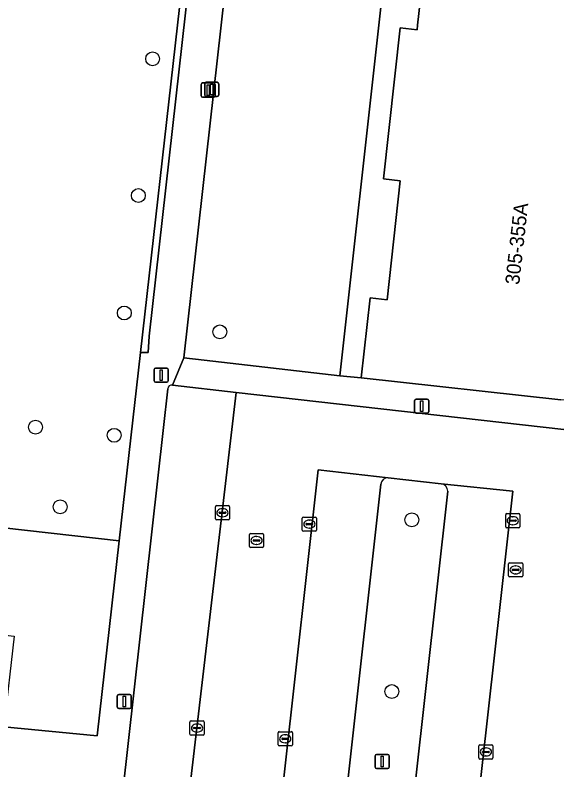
# Model space of a CAD drawing. Extents: x 161928 to 163071, y 386474 to 387428.
# Drawn here: x 162020.1 to 162058.3, y 386697.5 to 386750.7 of the extents above; entities that cross this region are included whole.
import ezdxf

# ---------------------------------------------------------------- set-up
doc = ezdxf.new("R2010")
doc.units = 0
for name, color, linetype in [('IMGEO_Boom', 7, 'Continuous'), ('IMGEO_Erf', 7, 'Continuous'), ('IMGEO_Groenvoorziening', 7, 'Continuous'), ('IMGEO_Kolk', 7, 'Continuous'), ('IMGEO_Lichtmast', 7, 'Continuous'), ('IMGEO_Pand', 7, 'Continuous'), ('IMGEO_Pand_nummerreeks', 7, 'Continuous'), ('IMGEO_Parkeervlak_open', 7, 'Continuous'), ('IMGEO_Rijbaan_lokaal_open', 7, 'Continuous'), ('IMGEO_Rioolput', 7, 'Continuous'), ('IMGEO_Voetpad_open', 7, 'Continuous')]:
    doc.layers.add(name, color=color, linetype=linetype)

msp = doc.modelspace()

# ---------------------------------------------------------------- linework, layer by layer
at = {"layer": 'IMGEO_Boom'}
for centre in [(162029.798, 386747.617), (162028.793, 386737.977), (162027.801, 386729.696), (162034.543, 386728.362), (162021.54, 386721.644), (162027.088, 386721.072), (162023.278, 386716.03), (162048.08, 386715.113), (162046.668, 386702.996)]:
    msp.add_circle(centre, 0.489, dxfattribs=at)
at = {"layer": 'IMGEO_Erf'}
msp.add_lwpolyline([(162044.512, 386725.13), (162045.14, 386730.766), (162046.333, 386730.634), (162047.268, 386739.022), (162046.075, 386739.154), (162047.261, 386749.807), (162048.454, 386749.675), (162048.49, 386750), (162049.389, 386758.073), (162048.195, 386758.205), (162048.824, 386763.85), (162047.299, 386764.081), (162045.743, 386750), (162043.01, 386725.268)], close=True, dxfattribs=at)
at = {"layer": 'IMGEO_Groenvoorziening'}
for points in [[(162031.554, 386750), (162033.319, 386765.609), (162026.736, 386766.372), (162021.82, 386766.942), (162021.773, 386766.325), (162007.448, 386767.992), (162006.241, 386755.742), (162005.304, 386755.813), (162005.214, 386755.021), (162004.653, 386750), (162000.921, 386716.619), (162027.442, 386713.619), (162028.943, 386726.903)], [(162045.743, 386750), (162047.299, 386764.081), (162036.361, 386765.29), (162034.645, 386750), (162032.012, 386726.545), (162033.433, 386726.38), (162043.01, 386725.268)], [(162027.442, 386713.619), (162000.921, 386716.619), (162000.892, 386716.355), (162002.809, 386716.141), (162002.552, 386713.863), (162018.281, 386712.103), (162017.75, 386707.17), (162020.04, 386706.893), (162019.314, 386700.509), (162025.888, 386699.876)]]:
    msp.add_lwpolyline(points, close=True, dxfattribs=at)
for points in [[(162050.156, 386717.652), (162046.414, 386718.074)], [(162045.889, 386717.614), (162041.265, 386675.985)], [(162045.986, 386675.583), (162050.625, 386717.141)]]:
    msp.add_lwpolyline(points, dxfattribs=at)
for centre, radius, start, end in [((162046.415, 386717.544), 0.53, 90.0572, 172.3919), ((162050.075, 386717.107), 0.551, 3.5466, 81.5454)]:
    msp.add_arc(centre, radius, start, end, dxfattribs=at)
at = {"layer": 'IMGEO_Kolk'}
for p, q in [((162034.223, 386715.183), (162034.223, 386716.035)), ((162034.298, 386716.109), (162035.15, 386716.109)), ((162034.711, 386715.889), (162034.736, 386715.889)), ((162035.224, 386716.035), (162035.224, 386715.183)), ((162034.482, 386715.603), (162034.482, 386715.615)), ((162034.92, 386715.566), (162034.522, 386715.566)), ((162034.525, 386715.652), (162034.923, 386715.652)), ((162034.734, 386715.329), (162034.709, 386715.329)), ((162034.966, 386715.615), (162034.966, 386715.603)), ((162040.355, 386714.38), (162040.355, 386715.232)), ((162040.43, 386715.306), (162041.282, 386715.306)), ((162041.356, 386715.232), (162041.356, 386714.38)), ((162054.697, 386714.621), (162054.697, 386715.473)), ((162054.772, 386715.547), (162055.624, 386715.547)), ((162055.185, 386715.327), (162055.21, 386715.327)), ((162055.698, 386715.473), (162055.698, 386714.621)), ((162035.15, 386715.109), (162034.298, 386715.109)), ((162040.614, 386714.8), (162040.614, 386714.812)), ((162041.052, 386714.763), (162040.654, 386714.763)), ((162040.657, 386714.849), (162041.055, 386714.849)), ((162040.843, 386715.086), (162040.868, 386715.086)), ((162041.098, 386714.812), (162041.098, 386714.8)), ((162054.956, 386715.041), (162054.956, 386715.053)), ((162055.394, 386715.004), (162054.996, 386715.004)), ((162054.999, 386715.09), (162055.397, 386715.09)), ((162055.208, 386714.767), (162055.183, 386714.767)), ((162055.44, 386715.053), (162055.44, 386715.041)), ((162041.282, 386714.306), (162040.43, 386714.306)), ((162040.866, 386714.526), (162040.841, 386714.526)), ((162055.624, 386714.547), (162054.772, 386714.547)), ((162032.433, 386699.998), (162032.433, 386700.85)), ((162032.508, 386700.924), (162033.36, 386700.924)), ((162033.434, 386700.85), (162033.434, 386699.998)), ((162032.692, 386700.418), (162032.692, 386700.43)), ((162033.13, 386700.381), (162032.732, 386700.381)), ((162032.735, 386700.467), (162033.133, 386700.467)), ((162032.921, 386700.704), (162032.946, 386700.704)), ((162033.176, 386700.43), (162033.176, 386700.418)), ((162033.36, 386699.924), (162032.508, 386699.924)), ((162032.944, 386700.144), (162032.919, 386700.144)), ((162038.654, 386699.243), (162038.654, 386700.095)), ((162038.729, 386700.169), (162039.581, 386700.169)), ((162039.142, 386699.949), (162039.167, 386699.949)), ((162039.655, 386700.095), (162039.655, 386699.243)), ((162038.913, 386699.663), (162038.913, 386699.675)), ((162039.351, 386699.626), (162038.953, 386699.626)), ((162038.956, 386699.712), (162039.354, 386699.712)), ((162039.165, 386699.389), (162039.14, 386699.389)), ((162039.397, 386699.675), (162039.397, 386699.663)), ((162052.873, 386699.239), (162053.725, 386699.239)), ((162039.581, 386699.169), (162038.729, 386699.169)), ((162052.798, 386698.313), (162052.798, 386699.165)), ((162053.057, 386698.733), (162053.057, 386698.745)), ((162053.495, 386698.696), (162053.097, 386698.696)), ((162053.1, 386698.782), (162053.498, 386698.782)), ((162053.286, 386699.019), (162053.311, 386699.019)), ((162053.541, 386698.745), (162053.541, 386698.733)), ((162053.799, 386699.165), (162053.799, 386698.313)), ((162053.725, 386698.239), (162052.873, 386698.239)), ((162053.309, 386698.459), (162053.284, 386698.459))]:
    msp.add_line(p, q, dxfattribs=at)
for points in [[(162034.223, 386715.183), (162034.223, 386716.035)], [(162034.298, 386716.109), (162035.15, 386716.109)], [(162035.224, 386716.035), (162035.224, 386715.183)], [(162040.355, 386714.38), (162040.355, 386715.232)], [(162040.43, 386715.306), (162041.282, 386715.306)], [(162041.356, 386715.232), (162041.356, 386714.38)], [(162054.697, 386714.621), (162054.697, 386715.473)], [(162054.772, 386715.547), (162055.624, 386715.547)], [(162055.698, 386715.473), (162055.698, 386714.621)], [(162035.15, 386715.109), (162034.298, 386715.109)], [(162041.282, 386714.306), (162040.43, 386714.306)], [(162055.624, 386714.547), (162054.772, 386714.547)], [(162032.433, 386699.998), (162032.433, 386700.85)], [(162032.508, 386700.924), (162033.36, 386700.924)], [(162033.434, 386700.85), (162033.434, 386699.998)], [(162033.36, 386699.924), (162032.508, 386699.924)], [(162038.654, 386699.243), (162038.654, 386700.095)], [(162038.729, 386700.169), (162039.581, 386700.169)], [(162039.655, 386700.095), (162039.655, 386699.243)], [(162052.873, 386699.239), (162053.725, 386699.239)], [(162039.581, 386699.169), (162038.729, 386699.169)], [(162052.798, 386698.313), (162052.798, 386699.165)], [(162053.799, 386699.165), (162053.799, 386698.313)], [(162053.725, 386698.239), (162052.873, 386698.239)]]:
    msp.add_lwpolyline(points, dxfattribs=at)
for centre, radius, start, end in [((162034.3, 386716.033), 0.0765, 91.552, 178.448), ((162034.3, 386716.033), 0.0765, 91.552, 178.448), ((162035.148, 386716.033), 0.0765, 1.552, 88.448), ((162035.148, 386716.033), 0.0765, 1.552, 88.448), ((162034.3, 386715.185), 0.0765, 181.552, 268.448), ((162034.3, 386715.185), 0.0765, 181.552, 268.448), ((162034.522, 386715.612), 0.0403, 85.8775, 175.7526), ((162034.519, 386715.602), 0.0366, 178.938, 274.7102), ((162034.923, 386715.609), 0.043, 264.8664, 352.4533), ((162034.927, 386715.614), 0.0386, 1.7309, 96.639), ((162035.148, 386715.185), 0.0765, 271.552, 358.448), ((162035.148, 386715.185), 0.0765, 271.552, 358.448), ((162040.432, 386715.23), 0.0765, 91.552, 178.448), ((162040.432, 386715.23), 0.0765, 91.552, 178.448), ((162041.28, 386715.23), 0.0765, 1.552, 88.448), ((162041.28, 386715.23), 0.0765, 1.552, 88.448), ((162054.774, 386715.471), 0.0765, 91.552, 178.448), ((162054.774, 386715.471), 0.0765, 91.552, 178.448), ((162055.622, 386715.471), 0.0765, 1.552, 88.448), ((162055.622, 386715.471), 0.0765, 1.552, 88.448), ((162040.654, 386714.809), 0.0403, 85.8775, 175.7526), ((162040.651, 386714.799), 0.0366, 178.938, 274.7102), ((162041.055, 386714.806), 0.043, 264.8664, 352.4533), ((162041.059, 386714.811), 0.0386, 1.7309, 96.639), ((162054.996, 386715.05), 0.0403, 85.8775, 175.7526), ((162054.993, 386715.04), 0.0366, 178.938, 274.7102), ((162055.397, 386715.047), 0.043, 264.8664, 352.4533), ((162055.401, 386715.052), 0.0386, 1.7309, 96.639), ((162040.432, 386714.382), 0.0765, 181.552, 268.448), ((162040.432, 386714.382), 0.0765, 181.552, 268.448), ((162041.28, 386714.382), 0.0765, 271.552, 358.448), ((162041.28, 386714.382), 0.0765, 271.552, 358.448), ((162054.774, 386714.623), 0.0765, 181.552, 268.448), ((162054.774, 386714.623), 0.0765, 181.552, 268.448), ((162055.622, 386714.623), 0.0765, 271.552, 358.448), ((162055.622, 386714.623), 0.0765, 271.552, 358.448), ((162032.51, 386700.848), 0.0765, 91.552, 178.448), ((162032.51, 386700.848), 0.0765, 91.552, 178.448), ((162033.358, 386700.848), 0.0765, 1.552, 88.448), ((162033.358, 386700.848), 0.0765, 1.552, 88.448), ((162032.732, 386700.427), 0.0403, 85.8775, 175.7526), ((162032.729, 386700.417), 0.0366, 178.938, 274.7102), ((162033.133, 386700.424), 0.043, 264.8664, 352.4533), ((162033.137, 386700.429), 0.0386, 1.7309, 96.639), ((162032.51, 386700), 0.0765, 181.552, 268.448), ((162032.51, 386700), 0.0765, 181.552, 268.448), ((162033.358, 386700), 0.0765, 271.552, 358.448), ((162033.358, 386700), 0.0765, 271.552, 358.448), ((162038.731, 386700.093), 0.0765, 91.552, 178.448), ((162038.731, 386700.093), 0.0765, 91.552, 178.448), ((162039.579, 386700.093), 0.0765, 1.552, 88.448), ((162039.579, 386700.093), 0.0765, 1.552, 88.448), ((162038.731, 386699.245), 0.0765, 181.552, 268.448), ((162038.731, 386699.245), 0.0765, 181.552, 268.448), ((162038.953, 386699.672), 0.0403, 85.8775, 175.7526), ((162038.95, 386699.662), 0.0366, 178.938, 274.7102), ((162039.354, 386699.669), 0.043, 264.8664, 352.4533), ((162039.358, 386699.674), 0.0386, 1.7309, 96.639), ((162039.579, 386699.245), 0.0765, 271.552, 358.448), ((162039.579, 386699.245), 0.0765, 271.552, 358.448), ((162052.875, 386699.163), 0.0765, 91.552, 178.448), ((162052.875, 386699.163), 0.0765, 91.552, 178.448), ((162053.723, 386699.163), 0.0765, 1.552, 88.448), ((162053.723, 386699.163), 0.0765, 1.552, 88.448), ((162053.097, 386698.742), 0.0403, 85.8775, 175.7526), ((162053.094, 386698.732), 0.0366, 178.938, 274.7102), ((162053.498, 386698.739), 0.043, 264.8664, 352.4533), ((162053.502, 386698.744), 0.0386, 1.7309, 96.639), ((162052.875, 386698.315), 0.0765, 181.552, 268.448), ((162052.875, 386698.315), 0.0765, 181.552, 268.448), ((162053.723, 386698.315), 0.0765, 271.552, 358.448), ((162053.723, 386698.315), 0.0765, 271.552, 358.448)]:
    msp.add_arc(centre, radius, start, end, dxfattribs=at)
for centre, major_axis, ratio, start_param, end_param in [((162034.71, 386715.609), (-0.387, 0.002), 0.722429, 4.712389, 7.853982), ((162034.735, 386715.609), (-0.39, 0.002), 0.717154, 1.570796, 4.712389), ((162055.184, 386715.047), (-0.387, 0.002), 0.722429, 4.712389, 7.853982), ((162055.209, 386715.047), (-0.39, 0.002), 0.717154, 1.570796, 4.712389), ((162040.842, 386714.806), (-0.387, 0.002), 0.722429, 4.712389, 7.853982), ((162040.867, 386714.806), (-0.39, 0.002), 0.717154, 1.570796, 4.712389), ((162032.92, 386700.424), (-0.387, 0.002), 0.722429, 4.712389, 7.853982), ((162032.945, 386700.424), (-0.39, 0.002), 0.717154, 1.570796, 4.712389), ((162039.141, 386699.669), (-0.387, 0.002), 0.722429, 4.712389, 7.853982), ((162039.166, 386699.669), (-0.39, 0.002), 0.717154, 1.570796, 4.712389), ((162053.285, 386698.739), (-0.387, 0.002), 0.722429, 4.712389, 7.853982), ((162053.31, 386698.739), (-0.39, 0.002), 0.717154, 1.570796, 4.712389)]:
    msp.add_ellipse(centre, major_axis=major_axis, ratio=ratio, start_param=start_param, end_param=end_param, dxfattribs=at)
at = {"layer": 'IMGEO_Lichtmast'}
for p, q in [((162033.228, 386745.019), (162033.228, 386745.819)), ((162033.228, 386745.819), (162033.228, 386745.019)), ((162033.328, 386745.919), (162034.118, 386745.919)), ((162034.118, 386745.919), (162033.328, 386745.919)), ((162033.47, 386745.068), (162033.47, 386745.868)), ((162033.47, 386745.868), (162033.47, 386745.068)), ((162033.57, 386745.968), (162034.36, 386745.968)), ((162034.36, 386745.968), (162033.57, 386745.968)), ((162034.218, 386745.819), (162034.218, 386745.019)), ((162034.218, 386745.019), (162034.218, 386745.819)), ((162034.46, 386745.868), (162034.46, 386745.068)), ((162034.46, 386745.068), (162034.46, 386745.868)), ((162034.118, 386744.919), (162033.328, 386744.919)), ((162033.328, 386744.919), (162034.118, 386744.919)), ((162034.36, 386744.968), (162033.57, 386744.968)), ((162033.57, 386744.968), (162034.36, 386744.968)), ((162029.908, 386724.916), (162029.908, 386725.716)), ((162029.908, 386725.716), (162029.908, 386724.916)), ((162030.008, 386725.816), (162030.798, 386725.816)), ((162030.798, 386725.816), (162030.008, 386725.816)), ((162030.898, 386725.716), (162030.898, 386724.916)), ((162030.898, 386724.916), (162030.898, 386725.716)), ((162030.798, 386724.816), (162030.008, 386724.816)), ((162030.008, 386724.816), (162030.798, 386724.816)), ((162048.279, 386722.73), (162048.279, 386723.53)), ((162048.279, 386723.53), (162048.279, 386722.73)), ((162048.379, 386723.63), (162049.169, 386723.63)), ((162049.169, 386723.63), (162048.379, 386723.63)), ((162049.269, 386723.53), (162049.269, 386722.73)), ((162049.269, 386722.73), (162049.269, 386723.53)), ((162049.169, 386722.63), (162048.379, 386722.63)), ((162048.379, 386722.63), (162049.169, 386722.63)), ((162027.308, 386701.9), (162027.308, 386702.7)), ((162027.308, 386702.7), (162027.308, 386701.9)), ((162027.408, 386702.8), (162028.198, 386702.8)), ((162028.198, 386702.8), (162027.408, 386702.8)), ((162028.298, 386702.7), (162028.298, 386701.9)), ((162028.298, 386701.9), (162028.298, 386702.7)), ((162028.198, 386701.8), (162027.408, 386701.8)), ((162027.408, 386701.8), (162028.198, 386701.8)), ((162045.489, 386697.665), (162045.489, 386698.465)), ((162045.489, 386698.465), (162045.489, 386697.665)), ((162045.589, 386698.565), (162046.379, 386698.565)), ((162046.379, 386698.565), (162045.589, 386698.565)), ((162046.479, 386698.465), (162046.479, 386697.665)), ((162046.479, 386697.665), (162046.479, 386698.465)), ((162046.379, 386697.565), (162045.589, 386697.565)), ((162045.589, 386697.565), (162046.379, 386697.565))]:
    msp.add_line(p, q, dxfattribs=at)
for points in [[(162033.648, 386745.794), (162033.798, 386745.794), (162033.798, 386745.044), (162033.648, 386745.044), (162033.648, 386745.794)], [(162033.89, 386745.843), (162034.04, 386745.843), (162034.04, 386745.093), (162033.89, 386745.093), (162033.89, 386745.843)], [(162030.328, 386725.691), (162030.478, 386725.691), (162030.478, 386724.941), (162030.328, 386724.941), (162030.328, 386725.691)], [(162048.699, 386723.505), (162048.849, 386723.505), (162048.849, 386722.755), (162048.699, 386722.755), (162048.699, 386723.505)], [(162027.728, 386702.675), (162027.878, 386702.675), (162027.878, 386701.925), (162027.728, 386701.925), (162027.728, 386702.675)], [(162045.909, 386698.44), (162046.059, 386698.44), (162046.059, 386697.69), (162045.909, 386697.69), (162045.909, 386698.44)]]:
    msp.add_lwpolyline(points, dxfattribs=at)
for centre, start, end in [((162033.328, 386745.819), 90, 180), ((162033.328, 386745.819), 90, 180), ((162033.57, 386745.868), 90, 180), ((162033.57, 386745.868), 90, 180), ((162034.118, 386745.819), 0, 90), ((162034.118, 386745.819), 360, 90), ((162034.36, 386745.868), 0, 90), ((162034.36, 386745.868), 360, 90), ((162033.328, 386745.019), 180, 270), ((162033.328, 386745.019), 180, 270), ((162033.57, 386745.068), 180, 270), ((162033.57, 386745.068), 180, 270), ((162034.118, 386745.019), 270, 0), ((162034.118, 386745.019), 270, 0), ((162034.36, 386745.068), 270, 0), ((162034.36, 386745.068), 270, 0), ((162030.008, 386725.716), 90, 180), ((162030.008, 386725.716), 90, 180), ((162030.798, 386725.716), 0, 90), ((162030.798, 386725.716), 360, 90), ((162030.008, 386724.916), 180, 270), ((162030.008, 386724.916), 180, 270), ((162030.798, 386724.916), 270, 0), ((162030.798, 386724.916), 270, 0), ((162048.379, 386723.53), 90, 180), ((162048.379, 386723.53), 90, 180), ((162049.169, 386723.53), 0, 90), ((162049.169, 386723.53), 360, 90), ((162048.379, 386722.73), 180, 270), ((162048.379, 386722.73), 180, 270), ((162049.169, 386722.73), 270, 0), ((162049.169, 386722.73), 270, 0), ((162027.408, 386702.7), 90, 180), ((162027.408, 386702.7), 90, 180), ((162028.198, 386702.7), 0, 90), ((162028.198, 386702.7), 360, 90), ((162027.408, 386701.9), 180, 270), ((162027.408, 386701.9), 180, 270), ((162028.198, 386701.9), 270, 0), ((162028.198, 386701.9), 270, 0), ((162045.589, 386698.465), 90, 180), ((162045.589, 386698.465), 90, 180), ((162046.379, 386698.465), 0, 90), ((162046.379, 386698.465), 360, 90), ((162045.589, 386697.665), 180, 270), ((162045.589, 386697.665), 180, 270), ((162046.379, 386697.665), 270, 0), ((162046.379, 386697.665), 270, 0)]:
    msp.add_arc(centre, 0.1, start, end, dxfattribs=at)
at = {"layer": 'IMGEO_Pand'}
msp.add_lwpolyline([(162062.945, 386762.278), (162048.824, 386763.85), (162048.195, 386758.205), (162049.389, 386758.073), (162048.49, 386750), (162048.454, 386749.675), (162047.261, 386749.807), (162046.075, 386739.154), (162047.268, 386739.022), (162046.333, 386730.634), (162045.14, 386730.766), (162044.512, 386725.13), (162058.594, 386723.562)], dxfattribs=at)
at = {"layer": 'IMGEO_Parkeervlak_open'}
for points in [[(162030.861, 386724.346), (162030.559, 386721.622), (162025.596, 386677.256), (162029.178, 386676.854), (162030.14, 386676.772), (162035.688, 386724.098)], [(162035.688, 386724.098), (162031.198, 386724.615)], [(162046.414, 386718.074), (162041.463, 386718.633), (162036.718, 386676.03), (162041.695, 386675.5)], [(162041.265, 386675.985), (162045.889, 386717.614)], [(162055.206, 386717.137), (162050.156, 386717.652)], [(162045.448, 386675.119), (162050.462, 386674.649), (162055.206, 386717.137)], [(162050.625, 386717.141), (162045.986, 386675.583)]]:
    msp.add_lwpolyline(points, dxfattribs=at)
for centre, radius, start, end in [((162031.164, 386724.312), 0.305, 83.6127, 173.5824), ((162046.415, 386717.544), 0.53, 90.0572, 172.3919), ((162050.075, 386717.107), 0.551, 3.5466, 81.5454)]:
    msp.add_arc(centre, radius, start, end, dxfattribs=at)
at = {"layer": 'IMGEO_Rijbaan_lokaal_open'}
msp.add_lwpolyline([(162061.719, 386721.152), (162035.688, 386724.098), (162030.14, 386676.772), (162029.178, 386676.854), (162025.596, 386677.256), (162021.441, 386677.722), (162020.162, 386677.862)], dxfattribs=at)
msp.add_lwpolyline([(162046.414, 386718.074), (162050.156, 386717.652), (162055.206, 386717.137), (162050.462, 386674.649), (162045.448, 386675.119), (162041.695, 386675.5), (162036.718, 386676.03), (162041.463, 386718.633)], close=True, dxfattribs=at)
at = {"layer": 'IMGEO_Rioolput'}
for p, q in [((162036.701, 386714.152), (162037.553, 386714.152)), ((162036.626, 386713.226), (162036.626, 386714.078)), ((162036.885, 386713.646), (162036.885, 386713.658)), ((162037.323, 386713.609), (162036.925, 386713.609)), ((162036.928, 386713.695), (162037.326, 386713.695)), ((162037.114, 386713.932), (162037.139, 386713.932)), ((162037.369, 386713.658), (162037.369, 386713.646)), ((162037.627, 386714.078), (162037.627, 386713.226)), ((162037.553, 386713.152), (162036.701, 386713.152)), ((162037.137, 386713.372), (162037.112, 386713.372)), ((162054.9, 386711.154), (162054.9, 386712.006)), ((162054.975, 386712.08), (162055.827, 386712.08)), ((162055.901, 386712.006), (162055.901, 386711.154)), ((162055.159, 386711.574), (162055.159, 386711.586)), ((162055.597, 386711.537), (162055.199, 386711.537)), ((162055.202, 386711.623), (162055.6, 386711.623)), ((162055.388, 386711.86), (162055.413, 386711.86)), ((162055.643, 386711.586), (162055.643, 386711.574)), ((162055.827, 386711.08), (162054.975, 386711.08)), ((162055.411, 386711.3), (162055.386, 386711.3))]:
    msp.add_line(p, q, dxfattribs=at)
for points in [[(162036.701, 386714.152), (162037.553, 386714.152)], [(162036.626, 386713.226), (162036.626, 386714.078)], [(162037.627, 386714.078), (162037.627, 386713.226)], [(162037.553, 386713.152), (162036.701, 386713.152)], [(162054.9, 386711.154), (162054.9, 386712.006)], [(162054.975, 386712.08), (162055.827, 386712.08)], [(162055.901, 386712.006), (162055.901, 386711.154)], [(162055.827, 386711.08), (162054.975, 386711.08)]]:
    msp.add_lwpolyline(points, dxfattribs=at)
for centre, radius, start, end in [((162036.703, 386714.076), 0.0765, 91.552, 178.448), ((162036.703, 386714.076), 0.0765, 91.552, 178.448), ((162037.551, 386714.076), 0.0765, 1.552, 88.448), ((162037.551, 386714.076), 0.0765, 1.552, 88.448), ((162036.925, 386713.655), 0.0403, 85.8775, 175.7526), ((162036.922, 386713.645), 0.0366, 178.938, 274.7102), ((162037.326, 386713.652), 0.043, 264.8664, 352.4533), ((162037.33, 386713.657), 0.0386, 1.7309, 96.639), ((162036.703, 386713.228), 0.0765, 181.552, 268.448), ((162036.703, 386713.228), 0.0765, 181.552, 268.448), ((162037.551, 386713.228), 0.0765, 271.552, 358.448), ((162037.551, 386713.228), 0.0765, 271.552, 358.448), ((162054.977, 386712.004), 0.0765, 91.552, 178.448), ((162054.977, 386712.004), 0.0765, 91.552, 178.448), ((162055.825, 386712.004), 0.0765, 1.552, 88.448), ((162055.825, 386712.004), 0.0765, 1.552, 88.448), ((162055.199, 386711.583), 0.0403, 85.8775, 175.7526), ((162055.196, 386711.573), 0.0366, 178.938, 274.7102), ((162055.6, 386711.58), 0.043, 264.8664, 352.4533), ((162055.604, 386711.585), 0.0386, 1.7309, 96.639), ((162054.977, 386711.156), 0.0765, 181.552, 268.448), ((162054.977, 386711.156), 0.0765, 181.552, 268.448), ((162055.825, 386711.156), 0.0765, 271.552, 358.448), ((162055.825, 386711.156), 0.0765, 271.552, 358.448)]:
    msp.add_arc(centre, radius, start, end, dxfattribs=at)
for centre, major_axis, ratio, start_param, end_param in [((162037.113, 386713.652), (-0.387, 0.002), 0.722429, 4.712389, 7.853982), ((162037.138, 386713.652), (-0.39, 0.002), 0.717154, 1.570796, 4.712389), ((162055.387, 386711.58), (-0.387, 0.002), 0.722429, 4.712389, 7.853982), ((162055.412, 386711.58), (-0.39, 0.002), 0.717154, 1.570796, 4.712389)]:
    msp.add_ellipse(centre, major_axis=major_axis, ratio=ratio, start_param=start_param, end_param=end_param, dxfattribs=at)
at = {"layer": 'IMGEO_Voetpad_open'}
msp.add_lwpolyline([(162006.777, 386769.017), (162006.74, 386768.689), (162021.82, 386766.942), (162026.736, 386766.372), (162033.319, 386765.609), (162031.554, 386750), (162028.943, 386726.903), (162029.484, 386726.918), (162029.566, 386728.062), (162033.754, 386765.523), (162033.803, 386765.933)], close=True, dxfattribs=at)
for points in [[(162033.754, 386765.523), (162029.566, 386728.062), (162029.484, 386726.918), (162028.943, 386726.903), (162027.442, 386713.619), (162025.888, 386699.876), (162019.314, 386700.509), (162017.593, 386700.805), (162014.158, 386701.186), (162013.711, 386697.164)], [(162031.198, 386724.615), (162032.012, 386726.545), (162034.645, 386750), (162036.361, 386765.29)], [(162044.512, 386725.13), (162043.01, 386725.268), (162033.433, 386726.38), (162032.012, 386726.545), (162031.198, 386724.615), (162035.688, 386724.098), (162061.719, 386721.152)], [(162062.204, 386718.733), (162063.546, 386718.588), (162064.603, 386722.927), (162060.836, 386723.344), (162058.594, 386723.562), (162044.512, 386725.13)], [(162020.162, 386677.862), (162021.441, 386677.722), (162025.596, 386677.256), (162030.559, 386721.622), (162030.861, 386724.346)]]:
    msp.add_lwpolyline(points, dxfattribs=at)
msp.add_arc((162031.164, 386724.312), 0.305, 83.6127, 173.5824, dxfattribs=at)

# ---------------------------------------------------------------- texts
at = {"layer": 'IMGEO_Pand_nummerreeks'}
msp.add_text('305-355A', height=1, rotation=83.6352, dxfattribs=at).set_placement((162055.649, 386731.649))

doc.saveas('drawing.dxf')
